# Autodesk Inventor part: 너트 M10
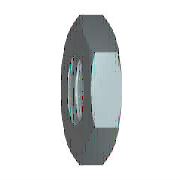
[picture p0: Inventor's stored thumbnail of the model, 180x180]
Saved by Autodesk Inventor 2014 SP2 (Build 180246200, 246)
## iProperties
IsCustomPart: 1
Created: 2012-02
Part Number: 너트 M10
Material: 스테인리스강
Description: 미터법 정밀 피치 스레드가 있는 6각 가는 너트(모따기됨)
Document SubType Name: Modeling
Standard: ISO 8675
Designer: mduedu
Standard Revision: Second edition 1999-08-15
Standards Organization: ISO
Language: ko-KR
Size Designation: M10 x 1
Categories: <MemberInstance><Categories><Category DisplayName="조임쇠" InternalName="e4da775c-781d-43d5-af7c-5136215cf5a6" Mnemonic="FSTN"><Category DisplayName="너트" InternalN
Density: 8.08 g/cm^3
Appearance: 기본값
Author: mduedu
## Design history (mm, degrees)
sketch "스케치1"
  geometry: L1 (-9.238, 0)-(-4.619, 8); L2 (-4.619, 8)-(4.619, 8); L3 (4.619, 8)-(9.238, 0); L4 (9.238, 0)-(4.619, -8); L5 (4.619, -8)-(-4.619, -8); L6 (-4.619, -8)-(-9.238, 0); 2 further points
  constraints: 12 end point, 1 coincident, 1 horizontal, 11 other
  dimensions: "d0" = 18.47521 distance of L3.end L1.start (= 1.1547 x SW)
extrude "본체" new body sketch "스케치1" distance "d1" = 5 (= KOH); taper "d2" = 0 deg
sketch "스케치2"
  geometry: L1 (0, 4.619)-(0, 9.238) reference; L2 (0, 9.238)-(5, 9.238) reference; L3 (5, 4.619)-(5, 9.238) reference; L4 (-1, 0)-(6, 0) reference; L5 (1.11, 9.238)-(0, 7.315); L6 (3.89, 9.238)-(5, 7.315)
  constraints: 4 end point, 4 point on line
  dimensions: "d3" = 30 deg angle of L1 L5 (= ANG1); "d4" = 30 deg angle of L3 L6 (= ANG2); "d5" = 14.63 diameter of L5.end L4 (= SW0); "d6" = 14.63 diameter of L6.end L4 (= SW01)
revolve "모따기1" sketch "스케치2" stored, may be unused: angle "d7" = 90 deg
sketch "스케치3"
  geometry: 4 further points
  constraints: 1 coincident, 1 other
hole "스레드" sketch "스케치3" at (0, 0) diameter "d25" = 8.91747; stored, may be unused: countersink angle "d29" = 82 deg, drill point angle "d31" = 118 deg; dims "d26" = 6, "d27" = 4, "d28" = 2, "d30" = 8
workaxis "Work Axis1"
workplane "Work Plane1"
body "Solid1"
chamfer "모따기2" distance "d8" = 0.54127 (= -0.5 x GD1 + 0.5 x NND); stored, may be unused: angle "d9" = 30 deg, second distance "d40" = 0.54127 (= -0.5 x GD1 + 0.5 x NND)
chamfer "모따기3" distance "d10" = 0.54127 (= -0.5 x GD1 + 0.5 x NND); stored, may be unused: angle "d11" = 30 deg, second distance "d41" = 0.54127 (= -0.5 x GD1 + 0.5 x NND)
other parameters: "ANG1" = 30 deg [user parameter; used in 1 equation term], "ANG2" = 30 deg [user parameter; used in 1 equation term], "KOH" = 5 [user parameter; used in 1 equation term], "SW" = 16 [user parameter; used in 1 equation term], "SW0" = 14.63 [user parameter; used in 2 equation terms], "SW01" = 14.63 (= SW0) [user parameter; used in 1 equation term], "GD1" = 8.91747 (computed from THREADDIA, PTC, TOA) [user parameter; used in 4 equation terms], "d13" = 0, "d14" = 0, "d39" = 0, "d42" = 0, "GUL" = 0.54127 (= 0.541266 x PTC) [user parameter], "TOA" = 30 deg [user parameter; used in 1 equation term], "PTC" = 1 [user parameter; used in 4 equation terms], "E0" = 17.77 [user parameter], "GAL" = 0.54127 (= 0.541266 x PTC) [user parameter]
